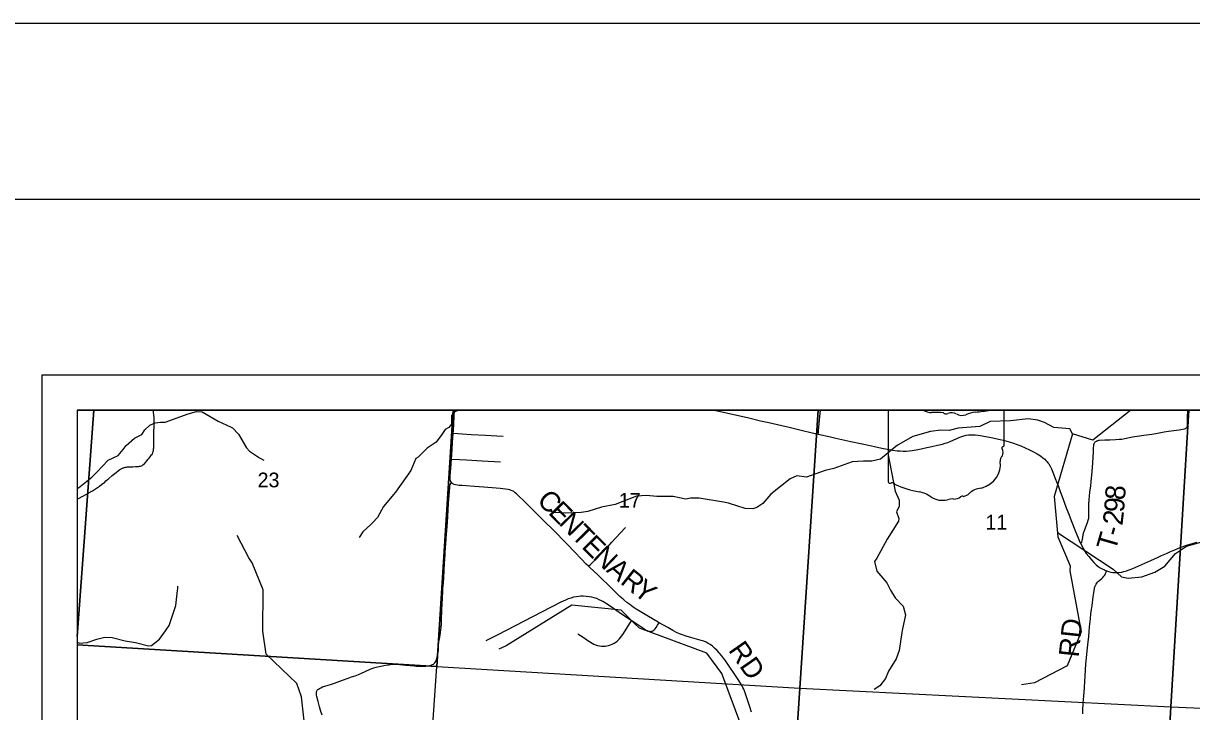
# Model space of a CAD drawing. Extents: x 0 to 34, y 0 to 22.
# Drawn here: x 1.947 to 5.267, y 20.043 to 22 of the extents above; entities that cross this region are included whole.
import ezdxf

# ---------------------------------------------------------------- set-up
doc = ezdxf.new("R2010")
doc.units = 0
for name, color, linetype in [('Default', 7, 'Continuous'), ('GM_X_County_Road', 7, 'Continuous'), ('GM_X_County_Road_Text', 7, 'Continuous'), ('GM_X_Minor_River', 7, 'Continuous'), ('GM_X_Section', 7, 'Continuous'), ('GM_X_Section_Text', 7, 'Continuous'), ('GM_X_State_Location', 7, 'Continuous'), ('GM_X_State_Route', 7, 'Continuous'), ('GM_X_Township_Road', 7, 'Continuous'), ('GM_X_Township_Road_Text', 7, 'Continuous'), ('SH_Border', 7, 'Continuous'), ('SH_Cut_Line', 7, 'Continuous'), ('SH_Data', 7, 'Continuous'), ('SH_Text', 7, 'Continuous')]:
    doc.layers.add(name, color=color, linetype=linetype)

msp = doc.modelspace()

# ---------------------------------------------------------------- linework, layer by layer
at = {"layer": 'Default'}
for p, q in [((4.4049, 20.8963), (4.4049, 20.6962)), ((4.5047, 20.8998), (4.4081, 20.8998))]:
    msp.add_line(p, q, dxfattribs=at)
for points in [[(2.1472, 20.9), (2.1, 20.9), (2.1, 20.2565)], [(2.1, 20.2565), (2.1, 20.233), (3.1221, 20.1708), (3.169, 20.9), (2.1472, 20.9)], [(4.206, 20.9), (3.169, 20.9), (3.1221, 20.1708), (4.1536, 20.1097)], [(5.259, 20.9), (4.206, 20.9), (4.1536, 20.1097), (5.2086, 20.056)], [(6.302, 20.9), (5.259, 20.9), (5.2086, 20.056), (6.2522, 20.0112)], [(2.1, 20.233), (2.1, 19.8081), (3.093, 19.7459), (3.1221, 20.1708)]]:
    msp.add_lwpolyline(points, close=True, dxfattribs=at)
for points in [[(6.0603, 16.8624), (6.127, 17.9511), (6.1612, 18.4732), (6.1665, 18.5542), (6.1773, 18.7192), (6.1898, 18.9313), (6.195, 19.011), (6.2406, 19.7849), (6.241, 19.7927), (6.2413, 19.8018), (6.2418, 19.8127), (6.2424, 19.8289), (6.2426, 19.8432), (6.2426, 19.8474), (6.2427, 19.8586), (6.2428, 19.8591), (6.2428, 19.8627), (6.2428, 19.867), (6.2428, 19.8705), (6.2431, 19.8748), (6.2438, 19.8792), (6.3032, 20.9), (2.1, 20.9), (2.1, 16.1239)], [(4.7345, 20.8001), (4.7345, 20.8001), (4.7345, 20.8), (4.7345, 20.9), (4.6949, 20.9)]]:
    msp.add_lwpolyline(points, dxfattribs=at)
for centre, major_axis, start_param, end_param in [((4.4087, 20.8968), (0.00382, 0), 1.727492, 3.291633), ((4.5277, 20.923), (0.037, 0), 4.042888, 4.731792), ((4.5399, 20.7874), (0.133, 0), 1.404758, 1.657859), ((4.5701, 20.8978), (0.0107, 0), 3.836095, 5.185415), ((4.5858, 20.8747), (0.0222, 0), 0.950623, 2.079405), ((4.6145, 20.9064), (0.0267, 0), 4.08156, 5.145723), ((4.6617, 20.8386), (0.0703, 0), 1.699012, 2.107814), ((4.6171, 21.1726), (0.3495, 0), 4.814394, 4.936803), ((4.7337, 20.7924), (0.00568, 0), 1.883978, 3.671073), ((4.6975, 20.7791), (0.0341, 0), 5.934695, 6.695948), ((4.7306, 20.7996), (0.00393, 0), 5.05454, 6.418171), ((4.6367, 20.7429), (0.0874, 0), 5.101753, 6.440018), ((4.7476, 20.7562), (0.0248, 0), 2.387724, 3.262537), ((4.4087, 20.6958), (0.00385, 0), 2.993084, 4.5083), ((4.4093, 20.7162), (0.0294, 0), 4.665946, 4.897461), ((4.4153, 20.6847), (0.0106, 0), 0.519207, 1.627899), ((4.5491, 20.8645), (0.2524, 0), 4.195997, 4.488961), ((4.4739, 20.6063), (0.079, 0), 0.823519, 1.323587), ((4.5593, 20.6837), (0.0501, 0), 4.026481, 4.996735), ((4.5919, 20.6687), (0.0267, 0), 4.691044, 5.507374), ((4.6161, 20.6493), (0.00752, 0), 1.147584, 2.315152), ((4.6129, 20.6768), (0.0282, 0), 4.937069, 5.64225), ((4.6735, 20.64), (0.0479, 0), 1.647645, 2.488434), ((4.5883, 20.6145), (0.0412, 0), 1.495662, 1.94098)]:
    msp.add_ellipse(centre, major_axis=major_axis, ratio=0.8, start_param=start_param, end_param=end_param, dxfattribs=at)
at = {"layer": 'GM_X_County_Road'}
msp.add_lwpolyline([(4.0169, 20.0414), (4.0117, 20.0567), (4.005, 20.0761), (3.9977, 20.0986), (3.9947, 20.1067), (3.9922, 20.1118), (3.9901, 20.1156), (3.9853, 20.1237), (3.9786, 20.1342), (3.9727, 20.1429), (3.9675, 20.1507), (3.9554, 20.1687), (3.9416, 20.1886), (3.9372, 20.1947), (3.9312, 20.2025), (3.9246, 20.2101), (3.9186, 20.2164), (3.9114, 20.2233), (3.9053, 20.2287), (3.8993, 20.2332), (3.8934, 20.2369), (3.8873, 20.2401), (3.8809, 20.2428), (3.8732, 20.2454), (3.8607, 20.2491), (3.8469, 20.2529), (3.8308, 20.2575), (3.8208, 20.2608), (3.8122, 20.2642), (3.8032, 20.2682), (3.7927, 20.2736), (3.7787, 20.2815), (3.7541, 20.2956), (3.7512, 20.2973), (3.7398, 20.3037), (3.7195, 20.3157), (3.6998, 20.3275), (3.6888, 20.3344), (3.6805, 20.3399), (3.6704, 20.3471), (3.6621, 20.3535), (3.6536, 20.3606), (3.6476, 20.3659), (3.6425, 20.3705), (3.6287, 20.3838), (3.6177, 20.3948), (3.6111, 20.4014), (3.5907, 20.4214), (3.5813, 20.4305), (3.5678, 20.4433), (3.5582, 20.4521), (3.5537, 20.4562), (3.5467, 20.4625), (3.5332, 20.4762), (3.5133, 20.4971), (3.4926, 20.5189), (3.4774, 20.5345), (3.4662, 20.5461), (3.453, 20.5593), (3.4284, 20.5838), (3.4173, 20.5948), (3.4004, 20.6112), (3.3911, 20.6204), (3.3746, 20.6372), (3.3672, 20.6447), (3.3587, 20.653), (3.3492, 20.6619), (3.3454, 20.6653), (3.3414, 20.6683), (3.3391, 20.6695), (3.3365, 20.6707), (3.3339, 20.6718), (3.3294, 20.6733), (3.3254, 20.6742), (3.3174, 20.6755), (3.3025, 20.677), (3.2914, 20.678), (3.2555, 20.6807), (3.2294, 20.6827), (3.2053, 20.6846), (3.1935, 20.6853), (3.1855, 20.686), (3.1812, 20.6865), (3.1757, 20.6875), (3.1717, 20.6887), (3.1695, 20.6897), (3.1679, 20.6906), (3.1666, 20.6915), (3.165, 20.693), (3.1637, 20.6944), (3.1622, 20.6969), (3.1615, 20.6985), (3.161, 20.7002), (3.1607, 20.702), (3.1604, 20.7056), (3.1606, 20.7124), (3.1621, 20.7353), (3.1639, 20.7609), (3.1648, 20.7731), (3.1671, 20.8068), (3.1691, 20.8348), (3.1693, 20.8406), (3.1705, 20.8611), (3.1719, 20.8822), (3.173, 20.8995), (3.173, 20.9)], dxfattribs=at)
at = {"layer": 'GM_X_Minor_River'}
for points in [[(2.1, 20.6785), (2.1038, 20.6796), (2.1421, 20.709), (2.1558, 20.7238), (2.1884, 20.7581), (2.2164, 20.771), (2.2308, 20.7885), (2.2392, 20.7999), (2.2627, 20.8205), (2.2843, 20.8308), (2.2923, 20.8437), (2.3063, 20.8578), (2.3222, 20.8639), (2.3366, 20.8654), (2.3499, 20.8655), (2.4158, 20.8899), (2.4397, 20.896), (2.4553, 20.8952), (2.5008, 20.8687), (2.5375, 20.852), (2.5421, 20.8493), (2.5587, 20.8322), (2.5811, 20.7931), (2.5898, 20.7836), (2.6182, 20.7646), (2.6311, 20.7582)], [(3.1846, 20.9), (3.1732, 20.8956), (3.1645, 20.8846), (3.1641, 20.8599), (3.1565, 20.8511), (3.1459, 20.845), (3.1368, 20.831), (3.1205, 20.8089), (3.0951, 20.7921), (3.0693, 20.7666), (3.0625, 20.7628), (3.0485, 20.7282), (3.0045, 20.6669), (2.9711, 20.6262), (2.9536, 20.595), (2.9407, 20.581), (2.9351, 20.5745), (2.9119, 20.5539), (2.9021, 20.5383)], [(5.0948, 20.9), (4.987, 20.8143), (4.929, 20.8331), (4.8767, 20.6546), (4.8873, 20.5397), (4.9222, 20.4577), (4.9212, 20.4433), (4.9539, 20.2701), (4.9138, 20.1726), (4.821, 20.1247), (4.7835, 20.1187)], [(4.929, 20.8331), (4.9211, 20.8465), (4.876, 20.851), (4.8495, 20.8647), (4.8301, 20.8715), (4.8025, 20.8749), (4.7528, 20.8699), (4.6944, 20.8676), (4.6652, 20.8539), (4.6531, 20.8527), (4.6035, 20.8492), (4.578, 20.842), (4.5545, 20.8427), (4.5257, 20.8389), (4.4753, 20.8251), (4.4336, 20.8011), (4.4264, 20.7962), (4.3836, 20.7608), (4.3589, 20.7554), (4.3347, 20.7554), (4.3024, 20.7527), (4.2509, 20.734), (4.2258, 20.7283), (4.1728, 20.7092), (4.1459, 20.7134), (4.1269, 20.7043), (4.0719, 20.6608), (4.0488, 20.6346), (4.0321, 20.6228), (4.02, 20.619), (3.9984, 20.6201), (3.951, 20.6352), (3.9373, 20.6387), (3.868, 20.6496), (3.8437, 20.6496), (3.8304, 20.6473), (3.7941, 20.6545), (3.7474, 20.6548), (3.7182, 20.6578), (3.6894, 20.6551), (3.6295, 20.6315), (3.5901, 20.6242), (3.5514, 20.6116), (3.5329, 20.6086), (3.4878, 20.607), (3.457, 20.6093), (3.4408, 20.6138)], [(4.4038, 20.7775), (4.4248, 20.6696), (4.4366, 20.6441), (4.4362, 20.6274), (4.429, 20.6107), (4.4354, 20.5917), (4.4343, 20.584), (4.4021, 20.5327), (4.3732, 20.4794), (4.3664, 20.4695), (4.3725, 20.4426), (4.4013, 20.4091), (4.4115, 20.3882), (4.4251, 20.3662), (4.4479, 20.343), (4.4539, 20.3179), (4.4444, 20.2734), (4.4437, 20.2681), (4.4364, 20.2168), (4.4277, 20.1928), (4.4057, 20.1575), (4.3974, 20.1369), (4.3811, 20.1156), (4.3655, 20.1061)], [(4.8862, 20.5519), (5.0445, 20.4475), (5.0679, 20.4257), (5.0873, 20.4221), (5.126, 20.4256), (5.1626, 20.4393), (5.1909, 20.456), (5.2212, 20.4928), (5.2532, 20.5133), (5.3235, 20.5335), (5.3459, 20.533), (5.3683, 20.5276), (5.4102, 20.5147), (5.4236, 20.5069), (5.4497, 20.4779), (5.4578, 20.4616), (5.4693, 20.4165)], [(2.7594, 19.8899), (2.7374, 20.0852), (2.7244, 20.123), (2.6371, 20.2057), (2.6275, 20.2713), (2.629, 20.389), (2.5973, 20.4654), (2.588, 20.4797), (2.5545, 20.5432)], [(2.1, 20.2402), (2.1071, 20.2375), (2.1287, 20.2394), (2.156, 20.2489), (2.1791, 20.2547), (2.2, 20.2536), (2.2363, 20.2437), (2.2663, 20.2392), (2.303, 20.2301), (2.3118, 20.2309), (2.3341, 20.2491), (2.3516, 20.2727), (2.3618, 20.2876), (2.3804, 20.3446), (2.3857, 20.3868), (2.3861, 20.3933), (2.3865, 20.3994)], [(4.1907, 18.8574), (4.1719, 18.9702), (4.1862, 19.0352), (4.1845, 19.1623), (4.1415, 19.2276), (4.075, 19.2911), (4.0757, 19.3594), (4.0541, 19.4097), (4.057, 19.5938), (4.0546, 19.6579), (4.0103, 19.7941), (3.9887, 19.9981), (3.9324, 20.1513), (3.8898, 20.2086), (3.6983, 20.2805), (3.6841, 20.2933), (3.6464, 20.3317), (3.5061, 20.3456), (3.3197, 20.2301), (3.2986, 20.2204)]]:
    msp.add_lwpolyline(points, dxfattribs=at)
at = {"layer": 'GM_X_Section'}
for points in [[(3.1221, 20.1708), (4.1536, 20.1097), (4.1266, 19.6923), (4.0998, 19.2759), (4.0875, 19.0909), (4.0872, 19.0874), (3.4908, 19.1174), (3.0501, 19.1382), (3.0637, 19.3317), (3.093, 19.7459)], [(4.1536, 20.1097), (5.2086, 20.056), (5.1842, 19.6356), (4.1266, 19.6923)], [(6.2522, 20.0112), (6.1895, 18.9865), (5.1485, 19.0298), (5.159, 19.2125), (5.1842, 19.6356), (5.2086, 20.056)]]:
    msp.add_lwpolyline(points, close=True, dxfattribs=at)
at = {"layer": 'GM_X_State_Route'}
for points in [[(3.9097, 20.9), (3.9234, 20.8969), (3.9452, 20.8923), (4.0088, 20.8778), (4.042, 20.8699), (4.0656, 20.8646), (4.1032, 20.8561), (4.1237, 20.8513), (4.1617, 20.842), (4.1848, 20.8368), (4.2062, 20.8318)], [(4.2062, 20.8318), (4.2411, 20.8239), (4.2563, 20.8206), (4.2993, 20.8111), (4.3266, 20.8054), (4.3539, 20.7993), (4.3696, 20.7959), (4.3921, 20.791), (4.4074, 20.788), (4.4178, 20.7863), (4.4302, 20.7847), (4.4389, 20.784), (4.4477, 20.7837), (4.4564, 20.7838), (4.4645, 20.7844), (4.4732, 20.7853), (4.4843, 20.7871), (4.4983, 20.7898), (4.5153, 20.7936), (4.5293, 20.7966), (4.5451, 20.8001), (4.559, 20.8035), (4.5668, 20.8058), (4.5744, 20.8085), (4.5831, 20.8119), (4.5979, 20.8184), (4.6082, 20.8228), (4.6175, 20.8262), (4.6264, 20.8285), (4.6336, 20.8297), (4.6373, 20.83), (4.6412, 20.8301), (4.6447, 20.8301), (4.6527, 20.8295), (4.6606, 20.8285), (4.6723, 20.8266), (4.6973, 20.8219), (4.7192, 20.8174), (4.7354, 20.8135), (4.7486, 20.8101), (4.7611, 20.8063), (4.7716, 20.8026), (4.782, 20.7985), (4.7939, 20.7933), (4.8067, 20.7871), (4.8183, 20.7811), (4.8285, 20.7754), (4.8375, 20.7698), (4.8445, 20.7649), (4.8502, 20.7602), (4.8533, 20.7572), (4.857, 20.7532), (4.8592, 20.7505), (4.8614, 20.7473), (4.8655, 20.7404), (4.8689, 20.7332), (4.8727, 20.724), (4.8796, 20.7061), (4.8887, 20.6829), (4.894, 20.669), (4.9002, 20.6515), (4.9049, 20.6386), (4.9112, 20.6224), (4.9183, 20.6046), (4.9255, 20.5867), (4.9375, 20.5554), (4.9448, 20.5369), (4.9501, 20.5249), (4.9517, 20.5215), (4.955, 20.5148), (4.9594, 20.5065), (4.9649, 20.4974), (4.968, 20.4927), (4.9748, 20.4838), (4.9824, 20.4747), (4.9896, 20.4669), (4.9963, 20.4603), (5.0015, 20.4558), (5.0072, 20.4519), (5.0132, 20.4485), (5.0195, 20.4456), (5.023, 20.4441), (5.0265, 20.4428), (5.0313, 20.4412), (5.0374, 20.4397), (5.0436, 20.4387), (5.0498, 20.4382), (5.0555, 20.4382), (5.0617, 20.4386), (5.0686, 20.4395), (5.0747, 20.4408), (5.0826, 20.443), (5.0903, 20.4456), (5.1007, 20.4498), (5.1257, 20.4608), (5.1517, 20.4727), (5.1721, 20.482), (5.1816, 20.4864), (5.1957, 20.4926), (5.2053, 20.4967), (5.2148, 20.5007), (5.2198, 20.5031), (5.2283, 20.5067), (5.2348, 20.5093), (5.2401, 20.5115), (5.2483, 20.5144), (5.2595, 20.5179), (5.2834, 20.5247)]]:
    msp.add_lwpolyline(points, dxfattribs=at)
at = {"layer": 'GM_X_Township_Road'}
for points in [[(2.1, 20.6466), (2.1021, 20.6476), (2.118, 20.6561), (2.1315, 20.6637), (2.1438, 20.671), (2.1553, 20.6785), (2.1635, 20.6841), (2.1694, 20.6886), (2.1785, 20.6957), (2.182, 20.6987), (2.1865, 20.7024), (2.1892, 20.7047), (2.2001, 20.7139), (2.2107, 20.7225), (2.2179, 20.7284), (2.2219, 20.7313), (2.225, 20.7332), (2.2269, 20.7343), (2.2291, 20.7353), (2.2305, 20.7359), (2.2324, 20.7364), (2.2346, 20.7371), (2.2367, 20.7376), (2.239, 20.738), (2.2405, 20.7382), (2.2435, 20.7385), (2.2476, 20.7388), (2.2584, 20.7393), (2.2656, 20.7396), (2.2706, 20.7398), (2.2745, 20.7402), (2.2771, 20.7405), (2.2801, 20.7411), (2.2826, 20.742), (2.2848, 20.7429), (2.2869, 20.7442), (2.29, 20.7466), (2.2913, 20.7478), (2.2945, 20.7514), (2.2992, 20.7573), (2.3013, 20.7601), (2.3044, 20.7637), (2.3099, 20.7705), (2.3118, 20.7728), (2.3129, 20.7743), (2.3141, 20.7765), (2.315, 20.7787), (2.3163, 20.7827), (2.3168, 20.7849), (2.3176, 20.7899), (2.3178, 20.7928), (2.318, 20.798), (2.318, 20.8002), (2.3179, 20.8073), (2.3185, 20.8337), (2.3191, 20.8572), (2.3194, 20.8681), (2.3191, 20.8756), (2.3189, 20.8797), (2.3185, 20.8853), (2.3182, 20.888), (2.3176, 20.8926), (2.3171, 20.8959), (2.3166, 20.8989), (2.3164, 20.9)], [(4.2062, 20.8318), (4.2066, 20.8367), (4.2072, 20.8422), (4.2108, 20.8818), (4.2124, 20.9)], [(4.989, 20.7983), (4.9897, 20.802), (4.9907, 20.805), (4.9918, 20.8073), (4.9927, 20.8088), (4.9937, 20.8099), (4.9951, 20.8113), (4.9967, 20.8123), (4.9996, 20.8135), (5.0015, 20.814), (5.0038, 20.8144), (5.0059, 20.8146), (5.0203, 20.8152), (5.0351, 20.8158), (5.0506, 20.8164), (5.0611, 20.8171), (5.0691, 20.818), (5.0776, 20.8194), (5.0996, 20.8237), (5.1124, 20.8262), (5.132, 20.8293), (5.1542, 20.8322), (5.1658, 20.834), (5.1897, 20.8382), (5.2013, 20.8399), (5.2167, 20.842), (5.2321, 20.8441), (5.2413, 20.8456), (5.2472, 20.8472), (5.2498, 20.8481), (5.2513, 20.8491), (5.2533, 20.8509), (5.2543, 20.8523), (5.255, 20.8537), (5.2554, 20.8554), (5.2556, 20.8571), (5.2559, 20.8632), (5.2561, 20.8824), (5.2565, 20.8972), (5.2566, 20.9)], [(3.1691, 20.8348), (3.1823, 20.8337), (3.194, 20.8328), (3.22, 20.8312), (3.2603, 20.8291), (3.2927, 20.8271), (3.3106, 20.8261)], [(4.9779, 20.6658), (4.9781, 20.6677), (4.9805, 20.6843), (4.9822, 20.6972), (4.9841, 20.7151), (4.986, 20.7368), (4.987, 20.7516), (4.9882, 20.7802), (4.9886, 20.7926), (4.989, 20.7983)], [(3.1639, 20.7609), (3.1872, 20.7593), (3.207, 20.7583), (3.2511, 20.7556), (3.3037, 20.7527)], [(2.7806, 20.0991), (2.781, 20.1006), (2.7816, 20.102), (2.7826, 20.1037), (2.7842, 20.1055), (2.7859, 20.107), (2.7886, 20.1086), (2.7925, 20.1105), (2.7976, 20.1128), (2.8066, 20.1159), (2.8201, 20.1203), (2.8312, 20.1241), (2.8545, 20.1326), (2.8708, 20.1382), (2.8802, 20.1412), (2.8901, 20.1447), (2.8994, 20.1483), (2.9079, 20.1521), (2.9309, 20.1629), (2.9378, 20.1658), (2.9431, 20.1676), (2.9504, 20.1694), (2.9629, 20.1722), (2.9764, 20.1746), (2.9856, 20.1762), (2.9931, 20.1773), (2.9971, 20.1775), (3.0003, 20.1776), (3.0066, 20.1775), (3.0165, 20.1768), (3.0344, 20.1752), (3.0462, 20.174), (3.0499, 20.1736), (3.0647, 20.1724), (3.0746, 20.1719), (3.0832, 20.172), (3.0907, 20.1723), (3.0956, 20.1728), (3.1011, 20.1737), (3.1058, 20.175), (3.1092, 20.1763), (3.1125, 20.1779), (3.1151, 20.1798), (3.1166, 20.1814), (3.119, 20.1847), (3.1203, 20.1874), (3.1211, 20.1896), (3.1226, 20.1949), (3.125, 20.2051), (3.1264, 20.2117), (3.1269, 20.2153), (3.1272, 20.22), (3.1273, 20.225), (3.1273, 20.2307), (3.1273, 20.2332), (3.1275, 20.2356), (3.1278, 20.2385), (3.1282, 20.2415), (3.1297, 20.2487), (3.131, 20.2549), (3.132, 20.2606), (3.133, 20.2685), (3.1345, 20.2818), (3.1353, 20.2928), (3.1357, 20.3008), (3.136, 20.3112), (3.1364, 20.3229), (3.1369, 20.3359), (3.1373, 20.3452), (3.1375, 20.3495), (3.1381, 20.3645), (3.1385, 20.3713), (3.139, 20.3799), (3.1397, 20.3904), (3.1404, 20.4013), (3.141, 20.4081), (3.142, 20.4235), (3.143, 20.4452), (3.144, 20.4638), (3.1456, 20.4892), (3.1462, 20.4985), (3.1467, 20.5059), (3.147, 20.5102), (3.1476, 20.5183), (3.1488, 20.535), (3.1522, 20.5802), (3.1558, 20.6348), (3.1575, 20.6583), (3.1589, 20.6801), (3.1596, 20.6858), (3.1603, 20.6887), (3.1617, 20.691), (3.1637, 20.6944)], [(4.9517, 20.5215), (4.9539, 20.5224), (4.9551, 20.5242), (4.9561, 20.5286), (4.9578, 20.5383), (4.9595, 20.5462), (4.9614, 20.5528), (4.9639, 20.5605), (4.9713, 20.5803), (4.9735, 20.5873), (4.9748, 20.5933), (4.9755, 20.5995), (4.9756, 20.6075), (4.9756, 20.6324), (4.976, 20.6454), (4.9768, 20.656), (4.9779, 20.6658)], [(3.5537, 20.4562), (3.5577, 20.4603), (3.5739, 20.4765), (3.5895, 20.4925), (3.6079, 20.5118), (3.6198, 20.5244), (3.6437, 20.5503), (3.6589, 20.5664)], [(4.9584, 20.0364), (4.9584, 20.0519), (4.9587, 20.0606), (4.9592, 20.0681), (4.9608, 20.0866), (4.9631, 20.1114), (4.9643, 20.1287), (4.9649, 20.1442), (4.9667, 20.1779), (4.9683, 20.1953), (4.9706, 20.216), (4.9724, 20.2327), (4.9751, 20.2568), (4.9764, 20.271), (4.9776, 20.2834), (4.9797, 20.3062), (4.9814, 20.3204), (4.9829, 20.3328), (4.9843, 20.3445), (4.9878, 20.3691), (4.9892, 20.3802), (4.9913, 20.3931), (4.9923, 20.3974), (4.9938, 20.4015), (4.9959, 20.4055), (4.9976, 20.4081), (5, 20.411), (5.0028, 20.4136), (5.0114, 20.4206), (5.0154, 20.4244), (5.0182, 20.4277), (5.0203, 20.4311), (5.0226, 20.4354), (5.0265, 20.4428)], [(3.2623, 20.2452), (3.2965, 20.2621), (3.4462, 20.3397), (3.4523, 20.3428), (3.4761, 20.3548), (3.4889, 20.361), (3.4963, 20.3641), (3.5039, 20.3667), (3.5116, 20.3688), (3.5194, 20.3704), (3.5261, 20.3714), (3.5316, 20.3718), (3.535, 20.3719), (3.5384, 20.3719), (3.5464, 20.3714), (3.555, 20.3704), (3.5622, 20.3691), (3.5688, 20.3674), (3.5758, 20.365), (3.5832, 20.362), (3.5893, 20.3591), (3.5958, 20.3555), (3.6048, 20.3501), (3.6147, 20.3437), (3.6409, 20.3259), (3.6759, 20.3023), (3.6767, 20.3018), (3.7103, 20.2789), (3.7156, 20.2755), (3.7201, 20.2731), (3.7231, 20.2719), (3.7256, 20.2713), (3.7288, 20.271), (3.7314, 20.2712), (3.734, 20.2718), (3.7364, 20.2727), (3.7392, 20.2745), (3.7412, 20.2762), (3.7433, 20.2786), (3.7459, 20.2822), (3.7498, 20.2886), (3.7541, 20.2956)], [(3.5231, 20.2641), (3.5379, 20.2542), (3.5484, 20.247), (3.5562, 20.2419), (3.5642, 20.237), (3.5686, 20.2346), (3.5733, 20.2327), (3.5793, 20.2308), (3.5849, 20.2297), (3.5899, 20.2291), (3.5955, 20.229), (3.6012, 20.2293), (3.6055, 20.23), (3.6105, 20.231), (3.6159, 20.2327), (3.6211, 20.2348), (3.6262, 20.2373), (3.631, 20.2403), (3.635, 20.2434), (3.6378, 20.2459), (3.6409, 20.2491), (3.6444, 20.2535), (3.6505, 20.2622), (3.6721, 20.2948), (3.6767, 20.3018)], [(2.7963, 20.033), (2.7929, 20.043), (2.7889, 20.0561), (2.7848, 20.0711), (2.7812, 20.0862), (2.7805, 20.0899), (2.7802, 20.0931), (2.7801, 20.095), (2.7802, 20.0971), (2.7806, 20.0991)]]:
    msp.add_lwpolyline(points, dxfattribs=at)
at = {"layer": 'SH_Border'}
msp.add_lwpolyline([(1.5, 21.5), (33.5, 21.5), (33.5, 0.5), (1.5, 0.5)], close=True, dxfattribs=at)
at = {"layer": 'SH_Cut_Line'}
msp.add_lwpolyline([(0, 0), (34, 0), (34, 22), (0, 22)], close=True, dxfattribs=at)
at = {"layer": 'SH_Data'}
for p, q in [((2, 21), (9, 21)), ((2, 21), (2, 14)), ((2.1, 20.9), (2.1, 14.1)), ((2.1, 20.9), (8.9, 20.9))]:
    msp.add_line(p, q, dxfattribs=at)
at = {"layer": 'SH_Text'}
msp.add_lwpolyline([(8.9, 20.9), (2.1, 20.9), (2.1, 14.1)], dxfattribs=at)

# ---------------------------------------------------------------- texts
at = {"layer": 'GM_X_County_Road_Text'}
for s, height, rotation, p in [('C', 0.0568, 314.3928, (3.4041, 20.6405)), ('E', 0.0568, 314.3922, (3.4368, 20.6072)), ('N', 0.0568, 314.3921, (3.4665, 20.5768)), ('T', 0.0568, 314.4094, (3.5015, 20.5411)), ('E', 0.0568, 314.8988, (3.5316, 20.5104)), ('N', 0.0568, 316.4436, (3.5628, 20.4791)), ('A', 0.0568, 319.5218, (3.6015, 20.4424)), ('R', 0.0568, 321.4007, (3.6411, 20.4086)), ('Y', 0.0568, 321.4851, (3.6777, 20.3795)), ('RD', 0.05682, 304.9108, (3.9491, 20.2175))]:
    msp.add_text(s, height=height, rotation=rotation, dxfattribs=at).set_placement(p)
at = {"layer": 'GM_X_Section_Text'}
for s, p in [('23', (2.6129, 20.6806)), ('17', (3.6396, 20.6228)), ('11', (4.6812, 20.5606))]:
    msp.add_text(s, height=0.04186, rotation=0, dxfattribs=at).set_placement(p)
at = {"layer": 'GM_X_State_Location'}
msp.add_text('588', height=0.000189, rotation=0, dxfattribs=at).set_placement((4.4991, 20.7692))
for s in ['s', 'r']:
    msp.add_text(s, height=0.000189, dxfattribs=at).set_placement((4.566, 20.783))
at = {"layer": 'GM_X_Township_Road_Text'}
for s, height, rotation, p in [('8', 0.0568, 85.6504, (5.0775, 20.6428)), ('9', 0.0568, 85.7618, (5.075, 20.6079)), ('2', 0.0568, 83.4454, (5.0707, 20.5706)), ('T', 0.0568, 73.7773, (5.0505, 20.4971)), ('-', 0.0568, 74.3163, (5.0625, 20.5385)), ('RD', 0.05682, 84.0946, (4.946, 20.1957))]:
    msp.add_text(s, height=height, rotation=rotation, dxfattribs=at).set_placement(p)

doc.saveas('drawing.dxf')
